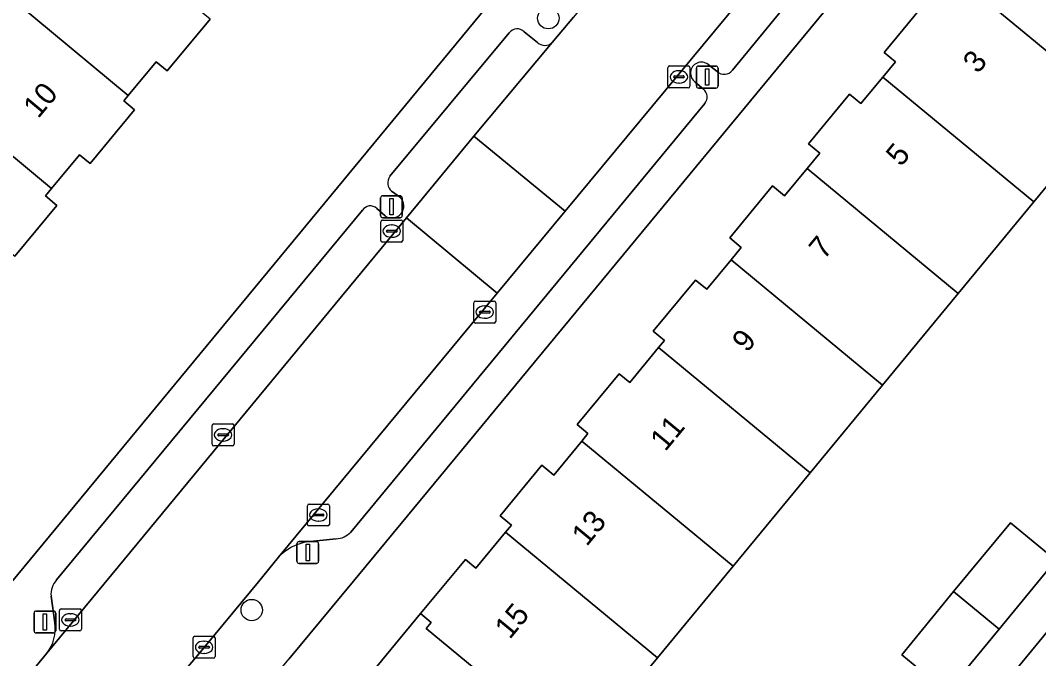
# Model space of a CAD drawing. Extents: x 162073 to 163043, y 381818 to 382561.
# Drawn here: x 162350.3 to 162396.77, y 382149.28 to 382178.43 of the extents above; entities that cross this region are included whole.
import ezdxf

# ---------------------------------------------------------------- set-up
doc = ezdxf.new("R2010")
doc.units = 0
for name, color, linetype in [('IMGEO_Boom', 7, 'Continuous'), ('IMGEO_Erf', 7, 'Continuous'), ('IMGEO_Kolk', 7, 'Continuous'), ('IMGEO_Lichtmast', 7, 'Continuous'), ('IMGEO_Pand', 7, 'Continuous'), ('IMGEO_Pand_nummerreeks', 7, 'Continuous'), ('IMGEO_Parkeervlak_open', 7, 'Continuous'), ('IMGEO_Rijbaan_lokaal_open', 7, 'Continuous'), ('IMGEO_Voetpad_open', 7, 'Continuous')]:
    doc.layers.add(name, color=color, linetype=linetype)

msp = doc.modelspace()

# ---------------------------------------------------------------- linework, layer by layer
at = {"layer": 'IMGEO_Boom'}
for centre in [(162374.396, 382178.527), (162360.862, 382151.5)]:
    msp.add_circle(centre, 0.489, dxfattribs=at)
at = {"layer": 'IMGEO_Erf'}
for points in [[(162397.464, 382191.526), (162365.499, 382152.814), (162362.554, 382149.261)], [(162345.338, 382147.264), (162373.579, 382181.474)], [(162365.645, 382147.796), (162368.566, 382151.337), (162370.609, 382153.813), (162371.094, 382153.413), (162372.445, 382155.049), (162372.709, 382155.369), (162372.192, 382155.795), (162374.101, 382158.109), (162374.64, 382157.665), (162375.917, 382159.213), (162376.204, 382159.561), (162375.711, 382159.968), (162377.624, 382162.287), (162378.107, 382161.889), (162379.422, 382163.483), (162379.695, 382163.814), (162379.185, 382164.234), (162381.114, 382166.571), (162381.625, 382166.15), (162382.733, 382167.493), (162383.201, 382168.06), (162382.675, 382168.494), (162384.631, 382170.866), (162385.177, 382170.416), (162386.201, 382171.657), (162386.783, 382172.362), (162386.27, 382172.785), (162388.144, 382175.057), (162388.663, 382174.628), (162389.656, 382175.832), (162390.24, 382176.54), (162389.723, 382176.967), (162391.662, 382179.316)], [(162358.959, 382178.487), (162357.002, 382176.116), (162356.496, 382176.533), (162355.227, 382174.996), (162355.02, 382174.745), (162355.508, 382174.343), (162353.483, 382171.889), (162352.999, 382172.289), (162351.729, 382170.751), (162351.447, 382170.409), (162351.966, 382169.98), (162350.045, 382167.653)], [(162400.165, 382174.522), (162396.544, 382170.133), (162393.096, 382165.953), (162389.648, 382161.773), (162386.338, 382157.761), (162382.823, 382153.5), (162379.373, 382149.317), (162376.035, 382145.271)], [(162363.474, 382144.097), (162379.006, 382131.297), (162385.618, 382139.32), (162383.544, 382141.028), (162385.913, 382143.906), (162388.503, 382147.051), (162390.577, 382145.343), (162392.595, 382147.754), (162390.521, 382149.462), (162392.89, 382152.34), (162395.48, 382155.485), (162397.554, 382153.777), (162399.374, 382155.928), (162397.3, 382157.636), (162399.67, 382160.515)]]:
    msp.add_lwpolyline(points, dxfattribs=at)
msp.add_lwpolyline([(162426.82, 382110.258), (162431.897, 382106.068), (162440.381, 382099.065), (162448.864, 382092.063), (162456.35, 382101.275), (162460.128, 382098.157), (162453.876, 382090.581), (162458.753, 382086.556), (162457.449, 382084.977), (162457.546, 382084.897), (162465.734, 382094.868), (162397.649, 382151.094), (162389.437, 382141.114), (162397.963, 382134.077), (162406.447, 382127.074), (162414.93, 382120.072), (162423.413, 382113.07), (162423.685, 382112.846), (162430.242, 382120.791), (162433.377, 382118.204)], close=True, dxfattribs=at)
at = {"layer": 'IMGEO_Kolk'}
for p, q in [((162379.856, 382175.42), (162379.856, 382176.272)), ((162379.931, 382176.346), (162380.783, 382176.346)), ((162380.344, 382176.126), (162380.369, 382176.126)), ((162380.857, 382176.272), (162380.857, 382175.42)), ((162380.115, 382175.84), (162380.115, 382175.852)), ((162380.553, 382175.803), (162380.155, 382175.803)), ((162380.158, 382175.889), (162380.556, 382175.889)), ((162380.599, 382175.852), (162380.599, 382175.84)), ((162380.783, 382175.346), (162379.931, 382175.346)), ((162380.367, 382175.566), (162380.342, 382175.566)), ((162366.749, 382168.378), (162366.749, 382169.23)), ((162366.824, 382169.304), (162367.676, 382169.304)), ((162367.237, 382169.084), (162367.262, 382169.084)), ((162367.75, 382169.23), (162367.75, 382168.378)), ((162367.008, 382168.798), (162367.008, 382168.81)), ((162367.446, 382168.761), (162367.048, 382168.761)), ((162367.051, 382168.847), (162367.449, 382168.847)), ((162367.492, 382168.81), (162367.492, 382168.798)), ((162367.676, 382168.304), (162366.824, 382168.304)), ((162367.26, 382168.524), (162367.235, 382168.524)), ((162370.994, 382164.68), (162370.994, 382165.532)), ((162371.069, 382165.606), (162371.921, 382165.606)), ((162371.482, 382165.386), (162371.507, 382165.386)), ((162371.995, 382165.532), (162371.995, 382164.68)), ((162371.253, 382165.1), (162371.253, 382165.112)), ((162371.691, 382165.063), (162371.293, 382165.063)), ((162371.296, 382165.149), (162371.694, 382165.149)), ((162371.737, 382165.112), (162371.737, 382165.1)), ((162371.921, 382164.606), (162371.069, 382164.606)), ((162371.505, 382164.826), (162371.48, 382164.826)), ((162359.052, 382159.072), (162359.052, 382159.924)), ((162359.127, 382159.998), (162359.979, 382159.998)), ((162359.54, 382159.778), (162359.565, 382159.778)), ((162360.053, 382159.924), (162360.053, 382159.072)), ((162359.311, 382159.492), (162359.311, 382159.504)), ((162359.749, 382159.455), (162359.351, 382159.455)), ((162359.354, 382159.541), (162359.752, 382159.541)), ((162359.795, 382159.504), (162359.795, 382159.492)), ((162359.979, 382158.998), (162359.127, 382158.998)), ((162359.563, 382159.218), (162359.538, 382159.218)), ((162363.403, 382155.413), (162363.403, 382156.265)), ((162363.478, 382156.339), (162364.33, 382156.339)), ((162363.891, 382156.119), (162363.916, 382156.119)), ((162364.404, 382156.265), (162364.404, 382155.413)), ((162363.662, 382155.833), (162363.662, 382155.845)), ((162364.1, 382155.796), (162363.702, 382155.796)), ((162363.705, 382155.882), (162364.103, 382155.882)), ((162364.146, 382155.845), (162364.146, 382155.833)), ((162364.33, 382155.339), (162363.478, 382155.339)), ((162363.914, 382155.559), (162363.889, 382155.559)), ((162352.088, 382150.625), (162352.088, 382151.477)), ((162352.163, 382151.551), (162353.015, 382151.551)), ((162353.089, 382151.477), (162353.089, 382150.625)), ((162352.347, 382151.045), (162352.347, 382151.057)), ((162352.785, 382151.008), (162352.387, 382151.008)), ((162352.39, 382151.094), (162352.788, 382151.094)), ((162352.576, 382151.331), (162352.601, 382151.331)), ((162352.831, 382151.057), (162352.831, 382151.045)), ((162353.015, 382150.551), (162352.163, 382150.551)), ((162352.599, 382150.771), (162352.574, 382150.771)), ((162358.188, 382149.375), (162358.188, 382150.227)), ((162358.263, 382150.301), (162359.115, 382150.301)), ((162358.676, 382150.081), (162358.701, 382150.081)), ((162359.189, 382150.227), (162359.189, 382149.375)), ((162358.447, 382149.795), (162358.447, 382149.807)), ((162358.885, 382149.758), (162358.487, 382149.758)), ((162358.49, 382149.844), (162358.888, 382149.844)), ((162358.931, 382149.807), (162358.931, 382149.795)), ((162359.115, 382149.301), (162358.263, 382149.301)), ((162358.699, 382149.521), (162358.674, 382149.521))]:
    msp.add_line(p, q, dxfattribs=at)
for points in [[(162379.856, 382175.42), (162379.856, 382176.272)], [(162379.931, 382176.346), (162380.783, 382176.346)], [(162380.857, 382176.272), (162380.857, 382175.42)], [(162380.783, 382175.346), (162379.931, 382175.346)], [(162366.749, 382168.378), (162366.749, 382169.23)], [(162366.824, 382169.304), (162367.676, 382169.304)], [(162367.75, 382169.23), (162367.75, 382168.378)], [(162367.676, 382168.304), (162366.824, 382168.304)], [(162370.994, 382164.68), (162370.994, 382165.532)], [(162371.069, 382165.606), (162371.921, 382165.606)], [(162371.995, 382165.532), (162371.995, 382164.68)], [(162371.921, 382164.606), (162371.069, 382164.606)], [(162359.052, 382159.072), (162359.052, 382159.924)], [(162359.127, 382159.998), (162359.979, 382159.998)], [(162360.053, 382159.924), (162360.053, 382159.072)], [(162359.979, 382158.998), (162359.127, 382158.998)], [(162363.403, 382155.413), (162363.403, 382156.265)], [(162363.478, 382156.339), (162364.33, 382156.339)], [(162364.404, 382156.265), (162364.404, 382155.413)], [(162364.33, 382155.339), (162363.478, 382155.339)], [(162352.088, 382150.625), (162352.088, 382151.477)], [(162352.163, 382151.551), (162353.015, 382151.551)], [(162353.089, 382151.477), (162353.089, 382150.625)], [(162353.015, 382150.551), (162352.163, 382150.551)], [(162358.188, 382149.375), (162358.188, 382150.227)], [(162358.263, 382150.301), (162359.115, 382150.301)], [(162359.189, 382150.227), (162359.189, 382149.375)], [(162359.115, 382149.301), (162358.263, 382149.301)]]:
    msp.add_lwpolyline(points, dxfattribs=at)
for centre, radius, start, end in [((162379.933, 382176.27), 0.0765, 91.552, 178.448), ((162379.933, 382176.27), 0.0765, 91.552, 178.448), ((162380.781, 382176.27), 0.0765, 1.552, 88.448), ((162380.781, 382176.27), 0.0765, 1.552, 88.448), ((162380.155, 382175.849), 0.0403, 85.8775, 175.7526), ((162380.152, 382175.839), 0.0366, 178.938, 274.7102), ((162380.556, 382175.846), 0.043, 264.8664, 352.4533), ((162380.56, 382175.851), 0.0386, 1.7309, 96.639), ((162379.933, 382175.422), 0.0765, 181.552, 268.448), ((162379.933, 382175.422), 0.0765, 181.552, 268.448), ((162380.781, 382175.422), 0.0765, 271.552, 358.448), ((162380.781, 382175.422), 0.0765, 271.552, 358.448), ((162366.826, 382169.228), 0.0765, 91.552, 178.448), ((162366.826, 382169.228), 0.0765, 91.552, 178.448), ((162367.674, 382169.228), 0.0765, 1.552, 88.448), ((162367.674, 382169.228), 0.0765, 1.552, 88.448), ((162367.048, 382168.807), 0.0403, 85.8775, 175.7526), ((162367.045, 382168.797), 0.0366, 178.938, 274.7102), ((162367.449, 382168.804), 0.043, 264.8664, 352.4533), ((162367.453, 382168.809), 0.0386, 1.7309, 96.639), ((162366.826, 382168.38), 0.0765, 181.552, 268.448), ((162366.826, 382168.38), 0.0765, 181.552, 268.448), ((162367.674, 382168.38), 0.0765, 271.552, 358.448), ((162367.674, 382168.38), 0.0765, 271.552, 358.448), ((162371.071, 382165.53), 0.0765, 91.552, 178.448), ((162371.071, 382165.53), 0.0765, 91.552, 178.448), ((162371.919, 382165.53), 0.0765, 1.552, 88.448), ((162371.919, 382165.53), 0.0765, 1.552, 88.448), ((162371.293, 382165.109), 0.0403, 85.8775, 175.7526), ((162371.29, 382165.099), 0.0366, 178.938, 274.7102), ((162371.694, 382165.106), 0.043, 264.8664, 352.4533), ((162371.698, 382165.111), 0.0386, 1.7309, 96.639), ((162371.071, 382164.682), 0.0765, 181.552, 268.448), ((162371.071, 382164.682), 0.0765, 181.552, 268.448), ((162371.919, 382164.682), 0.0765, 271.552, 358.448), ((162371.919, 382164.682), 0.0765, 271.552, 358.448), ((162359.129, 382159.922), 0.0765, 91.552, 178.448), ((162359.129, 382159.922), 0.0765, 91.552, 178.448), ((162359.977, 382159.922), 0.0765, 1.552, 88.448), ((162359.977, 382159.922), 0.0765, 1.552, 88.448), ((162359.351, 382159.501), 0.0403, 85.8775, 175.7526), ((162359.348, 382159.491), 0.0366, 178.938, 274.7102), ((162359.752, 382159.498), 0.043, 264.8664, 352.4533), ((162359.756, 382159.503), 0.0386, 1.7309, 96.639), ((162359.129, 382159.074), 0.0765, 181.552, 268.448), ((162359.129, 382159.074), 0.0765, 181.552, 268.448), ((162359.977, 382159.074), 0.0765, 271.552, 358.448), ((162359.977, 382159.074), 0.0765, 271.552, 358.448), ((162363.48, 382156.263), 0.0765, 91.552, 178.448), ((162363.48, 382156.263), 0.0765, 91.552, 178.448), ((162364.328, 382156.263), 0.0765, 1.552, 88.448), ((162364.328, 382156.263), 0.0765, 1.552, 88.448), ((162363.702, 382155.842), 0.0403, 85.8775, 175.7526), ((162363.699, 382155.832), 0.0366, 178.938, 274.7102), ((162364.103, 382155.839), 0.043, 264.8664, 352.4533), ((162364.107, 382155.844), 0.0386, 1.7309, 96.639), ((162363.48, 382155.415), 0.0765, 181.552, 268.448), ((162363.48, 382155.415), 0.0765, 181.552, 268.448), ((162364.328, 382155.415), 0.0765, 271.552, 358.448), ((162364.328, 382155.415), 0.0765, 271.552, 358.448), ((162352.165, 382151.475), 0.0765, 91.552, 178.448), ((162352.165, 382151.475), 0.0765, 91.552, 178.448), ((162353.013, 382151.475), 0.0765, 1.552, 88.448), ((162353.013, 382151.475), 0.0765, 1.552, 88.448), ((162352.387, 382151.054), 0.0403, 85.8775, 175.7526), ((162352.384, 382151.044), 0.0366, 178.938, 274.7102), ((162352.788, 382151.051), 0.043, 264.8664, 352.4533), ((162352.792, 382151.056), 0.0386, 1.7309, 96.639), ((162352.165, 382150.627), 0.0765, 181.552, 268.448), ((162352.165, 382150.627), 0.0765, 181.552, 268.448), ((162353.013, 382150.627), 0.0765, 271.552, 358.448), ((162353.013, 382150.627), 0.0765, 271.552, 358.448), ((162358.265, 382150.225), 0.0765, 91.552, 178.448), ((162358.265, 382150.225), 0.0765, 91.552, 178.448), ((162359.113, 382150.225), 0.0765, 1.552, 88.448), ((162359.113, 382150.225), 0.0765, 1.552, 88.448), ((162358.487, 382149.804), 0.0403, 85.8775, 175.7526), ((162358.484, 382149.794), 0.0366, 178.938, 274.7102), ((162358.888, 382149.801), 0.043, 264.8664, 352.4533), ((162358.892, 382149.806), 0.0386, 1.7309, 96.639), ((162358.265, 382149.377), 0.0765, 181.552, 268.448), ((162358.265, 382149.377), 0.0765, 181.552, 268.448), ((162359.113, 382149.377), 0.0765, 271.552, 358.448), ((162359.113, 382149.377), 0.0765, 271.552, 358.448)]:
    msp.add_arc(centre, radius, start, end, dxfattribs=at)
for centre, major_axis, ratio, start_param, end_param in [((162380.343, 382175.846), (-0.387, 0.002), 0.722429, 4.712389, 7.853982), ((162380.368, 382175.846), (-0.39, 0.002), 0.717154, 1.570796, 4.712389), ((162367.236, 382168.804), (-0.387, 0.002), 0.722429, 4.712389, 7.853982), ((162367.261, 382168.804), (-0.39, 0.002), 0.717154, 1.570796, 4.712389), ((162371.481, 382165.106), (-0.387, 0.002), 0.722429, 4.712389, 7.853982), ((162371.506, 382165.106), (-0.39, 0.002), 0.717154, 1.570796, 4.712389), ((162359.539, 382159.498), (-0.387, 0.002), 0.722429, 4.712389, 7.853982), ((162359.564, 382159.498), (-0.39, 0.002), 0.717154, 1.570796, 4.712389), ((162363.89, 382155.839), (-0.387, 0.002), 0.722429, 4.712389, 7.853982), ((162363.915, 382155.839), (-0.39, 0.002), 0.717154, 1.570796, 4.712389), ((162352.575, 382151.051), (-0.387, 0.002), 0.722429, 4.712389, 7.853982), ((162352.6, 382151.051), (-0.39, 0.002), 0.717154, 1.570796, 4.712389), ((162358.675, 382149.801), (-0.387, 0.002), 0.722429, 4.712389, 7.853982), ((162358.7, 382149.801), (-0.39, 0.002), 0.717154, 1.570796, 4.712389)]:
    msp.add_ellipse(centre, major_axis=major_axis, ratio=ratio, start_param=start_param, end_param=end_param, dxfattribs=at)
at = {"layer": 'IMGEO_Lichtmast'}
for p, q in [((162381.15, 382175.437), (162381.15, 382176.237)), ((162381.15, 382176.237), (162381.15, 382175.437)), ((162381.25, 382176.337), (162382.04, 382176.337)), ((162382.04, 382176.337), (162381.25, 382176.337)), ((162382.14, 382176.237), (162382.14, 382175.437)), ((162382.14, 382175.437), (162382.14, 382176.237)), ((162382.04, 382175.337), (162381.25, 382175.337)), ((162381.25, 382175.337), (162382.04, 382175.337)), ((162366.738, 382169.516), (162366.738, 382170.316)), ((162366.738, 382170.316), (162366.738, 382169.516)), ((162366.838, 382170.416), (162367.628, 382170.416)), ((162367.628, 382170.416), (162366.838, 382170.416)), ((162367.728, 382170.316), (162367.728, 382169.516)), ((162367.728, 382169.516), (162367.728, 382170.316)), ((162367.628, 382169.416), (162366.838, 382169.416)), ((162366.838, 382169.416), (162367.628, 382169.416)), ((162362.92, 382153.728), (162362.92, 382154.528)), ((162362.92, 382154.528), (162362.92, 382153.728)), ((162363.02, 382154.628), (162363.81, 382154.628)), ((162363.81, 382154.628), (162363.02, 382154.628)), ((162363.91, 382154.528), (162363.91, 382153.728)), ((162363.91, 382153.728), (162363.91, 382154.528)), ((162363.81, 382153.628), (162363.02, 382153.628)), ((162363.02, 382153.628), (162363.81, 382153.628)), ((162351.026, 382151.456), (162351.816, 382151.456)), ((162351.816, 382151.456), (162351.026, 382151.456)), ((162350.926, 382150.556), (162350.926, 382151.356)), ((162350.926, 382151.356), (162350.926, 382150.556)), ((162351.916, 382151.356), (162351.916, 382150.556)), ((162351.916, 382150.556), (162351.916, 382151.356)), ((162351.816, 382150.456), (162351.026, 382150.456)), ((162351.026, 382150.456), (162351.816, 382150.456))]:
    msp.add_line(p, q, dxfattribs=at)
for points in [[(162381.57, 382176.212), (162381.72, 382176.212), (162381.72, 382175.462), (162381.57, 382175.462), (162381.57, 382176.212)], [(162367.158, 382170.291), (162367.308, 382170.291), (162367.308, 382169.541), (162367.158, 382169.541), (162367.158, 382170.291)], [(162363.34, 382154.503), (162363.49, 382154.503), (162363.49, 382153.753), (162363.34, 382153.753), (162363.34, 382154.503)], [(162351.346, 382151.331), (162351.496, 382151.331), (162351.496, 382150.581), (162351.346, 382150.581), (162351.346, 382151.331)]]:
    msp.add_lwpolyline(points, dxfattribs=at)
for centre, start, end in [((162381.25, 382176.237), 90, 180), ((162381.25, 382176.237), 90, 180), ((162382.04, 382176.237), 0, 90), ((162382.04, 382176.237), 360, 90), ((162381.25, 382175.437), 180, 270), ((162381.25, 382175.437), 180, 270), ((162382.04, 382175.437), 270, 0), ((162382.04, 382175.437), 270, 0), ((162366.838, 382170.316), 90, 180), ((162366.838, 382170.316), 90, 180), ((162367.628, 382170.316), 0, 90), ((162367.628, 382170.316), 360, 90), ((162366.838, 382169.516), 180, 270), ((162366.838, 382169.516), 180, 270), ((162367.628, 382169.516), 270, 0), ((162367.628, 382169.516), 270, 0), ((162363.02, 382154.528), 90, 180), ((162363.02, 382154.528), 90, 180), ((162363.81, 382154.528), 0, 90), ((162363.81, 382154.528), 360, 90), ((162363.02, 382153.728), 180, 270), ((162363.02, 382153.728), 180, 270), ((162363.81, 382153.728), 270, 0), ((162363.81, 382153.728), 270, 0), ((162351.026, 382151.356), 90, 180), ((162351.026, 382151.356), 90, 180), ((162351.816, 382151.356), 0, 90), ((162351.816, 382151.356), 360, 90), ((162351.026, 382150.556), 180, 270), ((162351.026, 382150.556), 180, 270), ((162351.816, 382150.556), 270, 0), ((162351.816, 382150.556), 270, 0)]:
    msp.add_arc(centre, 0.1, start, end, dxfattribs=at)
at = {"layer": 'IMGEO_Pand'}
for points in [[(162348.305, 382180.751), (162355.227, 382174.996), (162356.496, 382176.533), (162357.002, 382176.116), (162358.959, 382178.487), (162358.484, 382178.879), (162358.759, 382179.212), (162351.806, 382184.992)], [(162403.752, 382178.871), (162396.912, 382184.626), (162395.724, 382183.185), (162395.199, 382183.618), (162393.224, 382181.223), (162393.731, 382180.804), (162393.261, 382180.234), (162400.165, 382174.522)], [(162348.305, 382180.751), (162344.804, 382176.509), (162351.729, 382170.751), (162352.999, 382172.289), (162353.483, 382171.889), (162355.508, 382174.343), (162355.02, 382174.745), (162355.227, 382174.996)], [(162389.656, 382175.832), (162396.544, 382170.133), (162400.165, 382174.522), (162393.261, 382180.234), (162392.163, 382178.903), (162391.662, 382179.316), (162389.723, 382176.967), (162390.24, 382176.54)], [(162348.226, 382166.51), (162349.524, 382168.083), (162350.045, 382167.653), (162351.966, 382169.98), (162351.447, 382170.409), (162351.729, 382170.751), (162344.804, 382176.509), (162341.302, 382172.267)], [(162389.656, 382175.832), (162388.663, 382174.628), (162388.144, 382175.057), (162386.27, 382172.785), (162386.783, 382172.362), (162386.201, 382171.657), (162393.096, 382165.953), (162396.544, 382170.133)], [(162382.733, 382167.493), (162389.648, 382161.773), (162393.096, 382165.953), (162386.201, 382171.657), (162385.177, 382170.416), (162384.631, 382170.866), (162382.675, 382168.494), (162383.201, 382168.06)], [(162379.422, 382163.483), (162386.338, 382157.761), (162389.648, 382161.773), (162382.733, 382167.493), (162381.625, 382166.15), (162381.114, 382166.571), (162379.185, 382164.234), (162379.695, 382163.814)], [(162379.422, 382163.483), (162378.107, 382161.889), (162377.624, 382162.287), (162375.711, 382159.968), (162376.204, 382159.561), (162375.917, 382159.213), (162382.823, 382153.5), (162386.338, 382157.761)], [(162379.373, 382149.317), (162382.823, 382153.5), (162375.917, 382159.213), (162374.64, 382157.665), (162374.101, 382158.109), (162372.192, 382155.795), (162372.709, 382155.369), (162372.445, 382155.049)], [(162392.89, 382152.34), (162394.961, 382150.627), (162397.554, 382153.777), (162395.48, 382155.485)], [(162379.373, 382149.317), (162372.445, 382155.049), (162371.094, 382153.413), (162370.609, 382153.813), (162368.566, 382151.337), (162369.049, 382150.938), (162368.82, 382150.661), (162375.737, 382144.939), (162376.035, 382145.271)], [(162392.89, 382152.34), (162390.521, 382149.462), (162392.595, 382147.754), (162394.961, 382150.627)], [(162368.566, 382151.337), (162365.645, 382147.796), (162377.647, 382137.895), (162380.615, 382141.493), (162376.035, 382145.271), (162375.737, 382144.939), (162368.82, 382150.661), (162369.049, 382150.938)]]:
    msp.add_lwpolyline(points, close=True, dxfattribs=at)
at = {"layer": 'IMGEO_Parkeervlak_open'}
for points in [[(162395.883, 382194.813), (162388.281, 382185.55), (162375.161, 382169.721), (162372.067, 382165.977), (162362.082, 382153.919)], [(162382.794, 382176.146), (162391.468, 382186.728), (162395.442, 382191.445)], [(162373.898, 382177.42), (162373.292, 382177.91)], [(162372.614, 382177.854), (162367.16, 382171.306)], [(162370.999, 382173.141), (162374.573, 382177.417)], [(162381.689, 382176.413), (162382.101, 382176.09)], [(162381.471, 382175.283), (162381.099, 382175.608)], [(162365.377, 382155.062), (162381.538, 382174.635)], [(162367.919, 382169.414), (162370.999, 382173.141)], [(162367.243, 382170.62), (162367.647, 382170.338)], [(162365.916, 382169.76), (162351.948, 382152.873)], [(162366.953, 382169.494), (162366.572, 382169.842)], [(162351.516, 382149.53), (162367.919, 382169.414)], [(162363.377, 382154.612), (162364.716, 382154.755)], [(162351.704, 382152.136), (162351.878, 382150.913)]]:
    msp.add_lwpolyline(points, dxfattribs=at)
for centre, radius, start, end in [((162372.977, 382177.592), 0.448, 45.2974, 144.1459), ((162374.237, 382177.771), 0.488, 225.9964, 313.4943), ((162381.384, 382176.018), 0.499, 52.2992, 235.224), ((162382.422, 382176.434), 0.47, 226.9684, 322.2715), ((162381.198, 382174.927), 0.448, 319.3269, 52.4794), ((162367.599, 382171.011), 0.529, 146.1314, 227.6661), ((162367.252, 382169.955), 0.55, 237.0173, 44.1235), ((162366.279, 382169.517), 0.437, 47.9653, 146.2848), ((162364.698, 382155.659), 0.904, 271.1333, 318.6915), ((162363.843, 382152.185), 2.472, 100.8685, 135.4371), ((162352.659, 382152.229), 0.959, 137.8078, 185.5557), ((162350.074, 382150.646), 1.824, 322.259, 8.4048)]:
    msp.add_arc(centre, radius, start, end, dxfattribs=at)
at = {"layer": 'IMGEO_Rijbaan_lokaal_open'}
msp.add_lwpolyline([(162403.616, 382205.939), (162400.109, 382208.829), (162398.977, 382207.405), (162394.607, 382201.927), (162393.345, 382200.337), (162392.521, 382199.353), (162391.67, 382198.337), (162391.469, 382198.07), (162387.133, 382192.747), (162382.421, 382186.948), (162380.42, 382184.465), (162375.549, 382178.578), (162374.573, 382177.417), (162370.999, 382173.141), (162375.161, 382169.721), (162388.281, 382185.55), (162395.883, 382194.813), (162396.623, 382195.74), (162397.535, 382196.883), (162398.84, 382198.394), (162403.183, 382203.671)], dxfattribs=at)
for points in [[(162372.067, 382165.977), (162375.161, 382169.721), (162370.999, 382173.141), (162367.919, 382169.414)], [(162335.106, 382129.564), (162339.238, 382126.178), (162344.927, 382133.085), (162345.792, 382134.155), (162351.1, 382140.57), (162357.27, 382148.101), (162357.867, 382148.812), (162358.381, 382149.422), (162361.17, 382152.783), (162362.082, 382153.919), (162372.067, 382165.977), (162367.919, 382169.414), (162351.516, 382149.53), (162349.496, 382147.059), (162343.976, 382140.371), (162342.788, 382138.891)]]:
    msp.add_lwpolyline(points, close=True, dxfattribs=at)
at = {"layer": 'IMGEO_Voetpad_open'}
for points in [[(162394.607, 382201.927), (162394.242, 382202.176), (162396.436, 382204.943), (162393.848, 382205.919), (162392.258, 382204.023), (162391.119, 382202.632), (162387.853, 382198.764), (162374.601, 382182.711), (162373.579, 382181.474), (162345.338, 382147.264), (162344.282, 382145.986), (162292.703, 382083.506), (162295.253, 382081.373), (162295.77, 382082.027)], [(162362.082, 382153.919), (162361.17, 382152.783), (162358.381, 382149.422), (162357.867, 382148.812), (162357.27, 382148.101), (162358.143, 382147.418), (162357.456, 382146.581), (162359.183, 382145.157), (162362.554, 382149.261), (162365.499, 382152.814), (162397.464, 382191.526)], [(162395.442, 382191.445), (162391.468, 382186.728), (162382.794, 382176.146)], [(162374.573, 382177.417), (162375.549, 382178.578)], [(162373.292, 382177.91), (162373.898, 382177.42)], [(162410.672, 382149.403), (162410.606, 382149.324), (162407.471, 382151.961), (162407.53, 382152.031), (162402.134, 382156.545), (162410.278, 382166.443), (162412.893, 382169.552), (162416.111, 382173.378), (162419.203, 382177.117), (162417.801, 382178.277), (162411.393, 382170.528), (162408.8, 382167.378), (162406.434, 382164.505), (162404.333, 382161.951), (162401.74, 382158.802), (162399.374, 382155.928), (162397.554, 382153.777), (162394.961, 382150.627), (162392.595, 382147.754)], [(162367.16, 382171.306), (162372.614, 382177.854)], [(162382.101, 382176.09), (162381.689, 382176.413)], [(162381.099, 382175.608), (162381.471, 382175.283)], [(162381.538, 382174.635), (162365.377, 382155.062)], [(162367.647, 382170.338), (162367.243, 382170.62)], [(162351.948, 382152.873), (162365.916, 382169.76)], [(162366.572, 382169.842), (162366.953, 382169.494)], [(162364.716, 382154.755), (162363.377, 382154.612)], [(162351.878, 382150.913), (162351.704, 382152.136)], [(162389.437, 382141.114), (162397.649, 382151.094), (162465.734, 382094.868)], [(162349.496, 382147.059), (162351.516, 382149.53)]]:
    msp.add_lwpolyline(points, dxfattribs=at)
for centre, radius, start, end in [((162372.977, 382177.592), 0.448, 45.2974, 144.1459), ((162374.237, 382177.771), 0.488, 225.9964, 313.4943), ((162381.384, 382176.018), 0.499, 52.2992, 235.224), ((162382.422, 382176.434), 0.47, 226.9684, 322.2715), ((162381.198, 382174.927), 0.448, 319.3269, 52.4794), ((162367.599, 382171.011), 0.529, 146.1314, 227.6661), ((162367.252, 382169.955), 0.55, 237.0173, 44.1235), ((162366.279, 382169.517), 0.437, 47.9653, 146.2848), ((162364.698, 382155.659), 0.904, 271.1333, 318.6915), ((162363.843, 382152.185), 2.472, 100.8685, 135.4371), ((162352.659, 382152.229), 0.959, 137.8078, 185.5557), ((162350.074, 382150.646), 1.824, 322.259, 8.4048)]:
    msp.add_arc(centre, radius, start, end, dxfattribs=at)

# ---------------------------------------------------------------- texts
at = {"layer": 'IMGEO_Pand_nummerreeks'}
for s, rotation, p in [('3', 50.4074, (162393.997, 382175.954)), ('10', 50.2589, (162351.12, 382173.911)), ('5', 50.4074, (162390.486, 382171.708)), ('7', 50.4074, (162386.974, 382167.462)), ('9', 50.4074, (162383.463, 382163.217)), ('11', 50.4074, (162379.731, 382158.705)), ('13', 50.4074, (162376.147, 382154.371)), ('15', 50.4074, (162372.635, 382150.126))]:
    msp.add_text(s, height=1, rotation=rotation, dxfattribs=at).set_placement(p)

doc.saveas('drawing.dxf')
